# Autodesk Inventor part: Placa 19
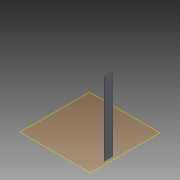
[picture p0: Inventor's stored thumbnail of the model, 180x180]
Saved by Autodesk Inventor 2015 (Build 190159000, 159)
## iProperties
Created: 2015-04
Part Number: Placa 19
Material: Generic
Document SubType Name: Modeling
Designer: suporte
Density: 1 g/cm^3
Appearance: Default
Author: suporte
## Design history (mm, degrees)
workplane "Work Plane1"
sketch "Sketch1"
  geometry: L1 (912.5, -500)-(900, -500); L2 (900, -500)-(900, -257.5); L3 (900, -257.5)-(912.5, -257.5); L4 (912.5, -257.5)-(912.5, -500); L5 (940.217, -270)-(959.783, -270) reference; L6 (912.5, -270)-(900, -270); 1 further point
  constraints: 10 end point, 2 parallel, 2 perpendicular, 2 point on line, 1 horizontal, 1 other
extrude "Extrusion1" new body sketch "Sketch1" distance "d0" = 2100; taper "d1" = 0 deg
body "Solid1"
node "Reference1"
node "Reference2"
